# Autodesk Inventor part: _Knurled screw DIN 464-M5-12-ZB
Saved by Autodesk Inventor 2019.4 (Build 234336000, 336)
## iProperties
Created: 2021-06
Part Number: _Knurled screw DIN 464-M5-12-ZB
Material: Generic
Document SubType Name: Modeling
Designer: Administrator
Density: 1 g/cm^3
Appearance: Default
Title: _Knurled screw DIN 464-M5-12-ZB
Author: Administrator
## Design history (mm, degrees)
feature "Body1"
body "Solid1"
